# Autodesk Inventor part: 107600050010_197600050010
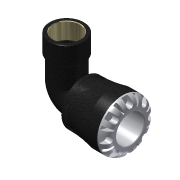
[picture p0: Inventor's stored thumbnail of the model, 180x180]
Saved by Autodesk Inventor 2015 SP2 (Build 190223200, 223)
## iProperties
Created: 2016-12
Part Number: 107600050010_197600050010
Material: PVC-Piping
Description: PLASSON 90° ELBOW WITH FEMALE INTEGRAL BRASS 50X1" SERIES 1
Document SubType Name: Modeling
Designer: KIM
Mass: 664.223 g
Surface Area: 733.008 cm^2
Volume: 474.445 cm^3
Density: 1.4 g/cm^3
Appearance: Black Cast
Author: KIM
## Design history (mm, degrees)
derived "1076.ipt"
feature "Solid1::1076.ipt"
tag "TaggingFeature1"
body "Solid1"
other parameters: "d1" = 33.18, "d3" = 62.5, "d4" = 85, "d8" = 74.8, "d13" = 9, "d14" = 9, "d15" = 0, "d17" = 360 deg, "d19" = 8 deg, "d20" = 1, "d21" = 1, "d22" = 8 deg, "d24" = 0, "d26" = 360 deg, "d33" = 8.5, "d51" = 0.85, "d54" = 17.5, "d55" = 11, "d57" = 17.64, "d58" = 0, "d74" = 0, "d78" = 79, "d82" = 1, "d115" = 360 deg, "d207" = 90 deg, "d228" = 14.875, "d248" = 4.74, "d270" = 122, "d281" = 4.54365, "d294" = 30.291, "d295" = 19, "d296" = 20.9, "d297" = 27.2619, "d299" = 35.44047, "d300" = 27.2619, "d301" = 0, "d302" = 0, "d306" = 1.96891, "d309" = 79.79, "d310" = 19.67977, "d312" = 15 deg, "d313" = 0.68, "d314" = 9.006, "d315" = 0.425, "E_" = 85, "l_" = 79, "A_" = 122, "l_2" = 19, "Rp_" = 30.291, "d9" = 11.25, "d11" = 85, "d12" = 62.5, "d298" = 39.3783
